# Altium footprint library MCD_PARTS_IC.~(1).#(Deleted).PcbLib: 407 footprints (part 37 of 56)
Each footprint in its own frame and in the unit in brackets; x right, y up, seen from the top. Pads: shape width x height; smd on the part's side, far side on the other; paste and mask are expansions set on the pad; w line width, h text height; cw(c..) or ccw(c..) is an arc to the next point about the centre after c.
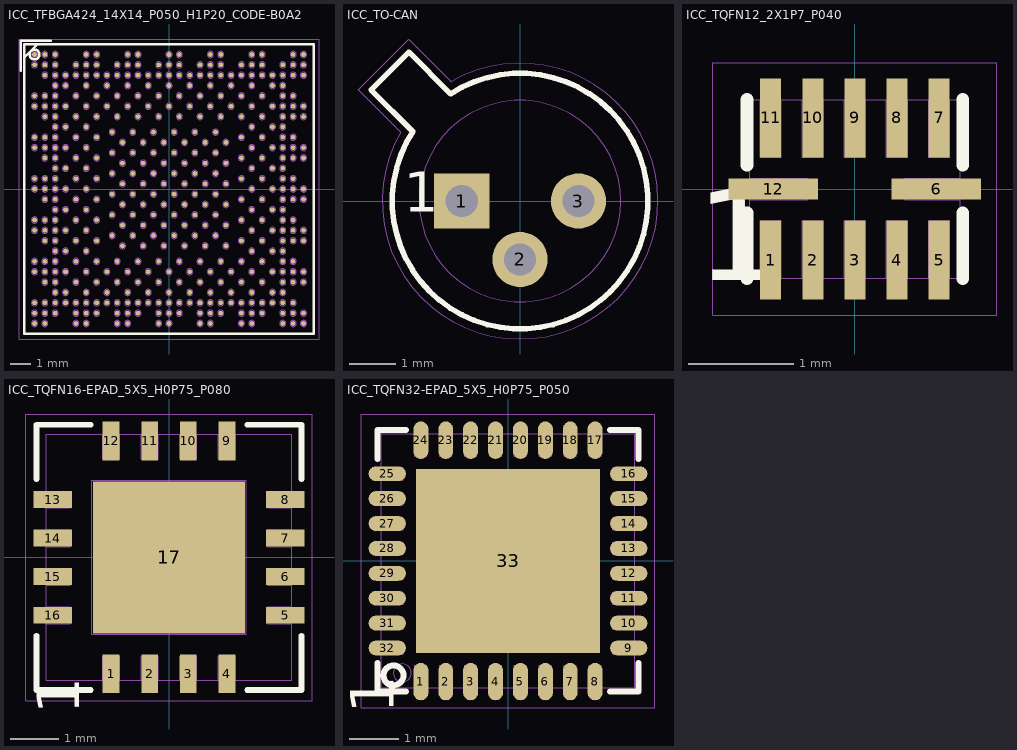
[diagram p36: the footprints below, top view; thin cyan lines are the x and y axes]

## ICC_TFBGA424_14X14_P050_H1P20_CODE-B0A2 [mm] "MCD_03375"
height 1.2
pads (424):
  round 0.23 smd paste+0.025 mask+0.05: 1A1(-2.75,2.75) 1A3(-1.75,2.75) 1A5(-0.75,2.75) 1A7(0.25,2.75) 1A9(1.25,2.75) 1A11(2.25,2.75) 1B2(-2.25,2.25) 1B4(-1.25,2.25) 1B6(-0.25,2.25) 1B8(0.75,2.25) 1B10(1.75,2.25) 1B12(2.75,2.25) 1C1(-2.75,1.75) 1C3(-1.75,1.75) 1C5(-0.75,1.75) 1C7(0.25,1.75) 1C9(1.25,1.75) 1C11(2.25,1.75) 1D2(-2.25,1.25) 1D4(-1.25,1.25) 1D6(-0.25,1.25) 1D8(0.75,1.25) 1D10(1.75,1.25) 1D12(2.75,1.25) 1E1(-2.75,0.75) 1E3(-1.75,0.75) 1E5(-0.75,0.75) 1E7(0.25,0.75) 1E9(1.25,0.75) 1E11(2.25,0.75) 1F2(-2.25,0.25) 1F4(-1.25,0.25) 1F6(-0.25,0.25) 1F8(0.75,0.25) 1F10(1.75,0.25) 1F12(2.75,0.25) 1G1(-2.75,-0.25) 1G3(-1.75,-0.25) 1G5(-0.75,-0.25) 1G7(0.25,-0.25) 1G9(1.25,-0.25) 1G11(2.25,-0.25) 1H2(-2.25,-0.75) 1H4(-1.25,-0.75) 1H6(-0.25,-0.75) 1H8(0.75,-0.75) 1H10(1.75,-0.75) 1H12(2.75,-0.75) 1J1(-2.75,-1.25) 1J3(-1.75,-1.25) 1J5(-0.75,-1.25) 1J7(0.25,-1.25) 1J9(1.25,-1.25) 1J11(2.25,-1.25) 1K2(-2.25,-1.75) 1K4(-1.25,-1.75) 1K6(-0.25,-1.75) 1K8(0.75,-1.75) 1K10(1.75,-1.75) 1K12(2.75,-1.75) 1L1(-2.75,-2.25) 1L3(-1.75,-2.25) 1L5(-0.75,-2.25) 1L7(0.25,-2.25) 1L9(1.25,-2.25) 1L11(2.25,-2.25) 1M2(-2.25,-2.75) 1M4(-1.25,-2.75) 1M6(-0.25,-2.75) 1M8(0.75,-2.75) 1M10(1.75,-2.75) 1M12(2.75,-2.75) A1(-6.5,6.5) A2(-6,6.5) A3(-5.5,6.5) A6(-4,6.5) A7(-3.5,6.5) A10(-2,6.5) A11(-1.5,6.5) A14(0,6.5) A15(0.5,6.5) A18(2,6.5) A19(2.5,6.5) A22(4,6.5) A23(4.5,6.5) A26(6,6.5) A27(6.5,6.5) AA1(-6.5,-3.5) AA2(-6,-3.5) AA3(-5.5,-3.5) AA5(-4.5,-3.5) AA7(-3.5,-3.5) AA9(-2.5,-3.5) AA11(-1.5,-3.5) AA13(-0.5,-3.5) AA15(0.5,-3.5) AA17(1.5,-3.5) AA19(2.5,-3.5) AA21(3.5,-3.5) AA23(4.5,-3.5) AA25(5.5,-3.5) AA26(6,-3.5) AB1(-6.5,-4) AB2(-6,-4) AB3(-5.5,-4) AB4(-5,-4) AB6(-4,-4) AB8(-3,-4) AB10(-2,-4) AB12(-1,-4) AB14(0,-4) AB16(1,-4) AB18(2,-4) AB20(3,-4) AB22(4,-4) AB24(5,-4) AB25(5.5,-4) AB26(6,-4) AB27(6.5,-4) AC2(-6,-4.5) AC3(-5.5,-4.5) AC5(-4.5,-4.5) AC7(-3.5,-4.5) AC9(-2.5,-4.5) AC11(-1.5,-4.5) AC13(-0.5,-4.5) AC15(0.5,-4.5) AC17(1.5,-4.5) AC19(2.5,-4.5) AC21(3.5,-4.5) AC23(4.5,-4.5) AC25(5.5,-4.5) AC26(6,-4.5) AC27(6.5,-4.5) AD3(-5.5,-5) AD4(-5,-5) AD6(-4,-5) AD8(-3,-5) AD10(-2,-5) AD12(-1,-5) AD14(0,-5) AD16(1,-5) AD18(2,-5) AD20(3,-5) AD22(4,-5) AD24(5,-5) AD25(5.5,-5) AE1(-6.5,-5.5) AE2(-6,-5.5) AE3(-5.5,-5.5) AE4(-5,-5.5) AE5(-4.5,-5.5) AE6(-4,-5.5) AE7(-3.5,-5.5) AE8(-3,-5.5) AE9(-2.5,-5.5) AE10(-2,-5.5) AE11(-1.5,-5.5) AE12(-1,-5.5) AE13(-0.5,-5.5) AE14(0,-5.5) AE15(0.5,-5.5) AE16(1,-5.5) AE17(1.5,-5.5) AE18(2,-5.5) AE19(2.5,-5.5) AE20(3,-5.5) AE21(3.5,-5.5) AE22(4,-5.5) AE23(4.5,-5.5) AE24(5,-5.5) AE25(5.5,-5.5) AE26(6,-5.5) AF1(-6.5,-6) AF2(-6,-6) AF3(-5.5,-6) AF5(-4.5,-6) AF6(-4,-6) AF7(-3.5,-6) AF9(-2.5,-6) AF10(-2,-6) AF11(-1.5,-6) AF13(-0.5,-6) AF14(0,-6) AF15(0.5,-6) AF17(1.5,-6) AF18(2,-6) AF19(2.5,-6) AF21(3.5,-6) AF22(4,-6) AF23(4.5,-6) AF25(5.5,-6) AF26(6,-6) AF27(6.5,-6) AG1(-6.5,-6.5) AG2(-6,-6.5) AG5(-4.5,-6.5) AG6(-4,-6.5) AG9(-2.5,-6.5) AG10(-2,-6.5) AG13(-0.5,-6.5) AG14(0,-6.5) AG17(1.5,-6.5) AG18(2,-6.5) AG21(3.5,-6.5) AG22(4,-6.5) AG25(5.5,-6.5) AG26(6,-6.5) AG27(6.5,-6.5) B1(-6.5,6) B2(-6,6) B3(-5.5,6) B5(-4.5,6) B6(-4,6) B7(-3.5,6) B9(-2.5,6) B10(-2,6) B11(-1.5,6) B13(-0.5,6) B14(0,6) B15(0.5,6) B17(1.5,6) B18(2,6) B19(2.5,6) B21(3.5,6) B22(4,6) B23(4.5,6) B25(5.5,6) B26(6,6) B27(6.5,6) C2(-6,5.5) C3(-5.5,5.5) C4(-5,5.5) C5(-4.5,5.5) C6(-4,5.5) C7(-3.5,5.5) C8(-3,5.5) C9(-2.5,5.5) C10(-2,5.5) C11(-1.5,5.5) C12(-1,5.5) C13(-0.5,5.5) C14(0,5.5) C15(0.5,5.5) C16(1,5.5) C17(1.5,5.5) C18(2,5.5) C19(2.5,5.5) C20(3,5.5) C21(3.5,5.5) C22(4,5.5) C23(4.5,5.5) C24(5,5.5) C25(5.5,5.5) C26(6,5.5) C27(6.5,5.5) D3(-5.5,5) D4(-5,5) D6(-4,5) D8(-3,5) D10(-2,5) D12(-1,5) D14(0,5) D16(1,5) D18(2,5) D20(3,5) D22(4,5) D24(5,5) D25(5.5,5) E1(-6.5,4.5) E2(-6,4.5) E3(-5.5,4.5) E5(-4.5,4.5) E7(-3.5,4.5) E9(-2.5,4.5) E11(-1.5,4.5) E13(-0.5,4.5) E15(0.5,4.5) E17(1.5,4.5) E19(2.5,4.5) E21(3.5,4.5) E23(4.5,4.5) E25(5.5,4.5) E26(6,4.5) F1(-6.5,4) F2(-6,4) F3(-5.5,4) F4(-5,4) F6(-4,4) F8(-3,4) F10(-2,4) F12(-1,4) F14(0,4) F16(1,4) F18(2,4) F20(3,4) F22(4,4) F24(5,4) F25(5.5,4) F26(6,4) F27(6.5,4) G2(-6,3.5) G3(-5.5,3.5) G5(-4.5,3.5) G7(-3.5,3.5) G9(-2.5,3.5) G11(-1.5,3.5) G13(-0.5,3.5) G15(0.5,3.5) G17(1.5,3.5) G19(2.5,3.5) G21(3.5,3.5) G23(4.5,3.5) G25(5.5,3.5) G26(6,3.5) G27(6.5,3.5) H3(-5.5,3) H4(-5,3) H6(-4,3) H22(4,3) H24(5,3) H25(5.5,3) J1(-6.5,2.5) J2(-6,2.5) J3(-5.5,2.5) J5(-4.5,2.5) J7(-3.5,2.5) J21(3.5,2.5) J23(4.5,2.5) J25(5.5,2.5) J26(6,2.5) K1(-6.5,2) K2(-6,2) K3(-5.5,2) K4(-5,2) K6(-4,2) K22(4,2) K24(5,2) K25(5.5,2) K26(6,2) K27(6.5,2) L2(-6,1.5) L3(-5.5,1.5) L5(-4.5,1.5) L7(-3.5,1.5) L21(3.5,1.5) L23(4.5,1.5) L25(5.5,1.5) L26(6,1.5) L27(6.5,1.5) M3(-5.5,1) M4(-5,1) M6(-4,1) M22(4,1) M24(5,1) M25(5.5,1) N1(-6.5,0.5) N2(-6,0.5) N3(-5.5,0.5) N5(-4.5,0.5) N7(-3.5,0.5) N21(3.5,0.5) N23(4.5,0.5) N25(5.5,0.5) N26(6,0.5) P1(-6.5,0) P2(-6,0) P3(-5.5,0) P4(-5,0) P6(-4,0) P22(4,0) P24(5,0) P25(5.5,0) P26(6,0) P27(6.5,0) R2(-6,-0.5) R3(-5.5,-0.5) R5(-4.5,-0.5) R7(-3.5,-0.5) R21(3.5,-0.5) R23(4.5,-0.5) R25(5.5,-0.5) R26(6,-0.5) R27(6.5,-0.5) T3(-5.5,-1) T4(-5,-1) T6(-4,-1) T22(4,-1) T24(5,-1) T25(5.5,-1) U1(-6.5,-1.5) U2(-6,-1.5) U3(-5.5,-1.5) U5(-4.5,-1.5) U7(-3.5,-1.5) U21(3.5,-1.5) U23(4.5,-1.5) U25(5.5,-1.5) U26(6,-1.5) V1(-6.5,-2) V2(-6,-2) V3(-5.5,-2) V4(-5,-2) V6(-4,-2) V22(4,-2) V24(5,-2) V25(5.5,-2) V26(6,-2) V27(6.5,-2) W2(-6,-2.5) W3(-5.5,-2.5) W5(-4.5,-2.5) W7(-3.5,-2.5) W21(3.5,-2.5) W23(4.5,-2.5) W25(5.5,-2.5) W26(6,-2.5) W27(6.5,-2.5) Y3(-5.5,-3) Y4(-5,-3) Y6(-4,-3) Y22(4,-3) Y24(5,-3) Y25(5.5,-3)
Top Overlay:
  circle w0.12: c-6.5,6.5 r0.24
  lines w0.12: -7.175,5.725 -7.175,7.175 -5.725,7.175 ; -7,6.345 -6.345,7 ; -7,-7 -7,7 7,7 7,-7 -7,-7
M14-Top Assembly:
  drawing of 429 lines, arcs and shapes, not listed
  text "'.Designator'" at 0,0 h0.75
  text "A1" at -6.75,6.3 h0.4
M16-Top Courtyard:
  lines w0.01: -7.25,-7.25 7.25,-7.25 7.25,7.25 -7.25,7.25 -7.25,-7.25
3D body: height 0.27, standoff -0.03, extent -2.4,-0.898 -2.109,-0.603
3D body: height 0.27, standoff -0.03, extent 0.1,-0.398 0.391,-0.103
3D body: height 0.27, standoff -0.03, extent -0.4,0.102 -0.109,0.397
3D body: height 0.27, standoff -0.03, extent 1.1,-0.398 1.391,-0.103
3D body: height 0.27, standoff -0.03, extent -0.9,-0.398 -0.609,-0.103
3D body: height 0.27, standoff -0.03, extent -1.9,-0.398 -1.609,-0.103
3D body: height 0.27, standoff -0.03, extent -2.9,-0.398 -2.609,-0.103
3D body: height 0.27, standoff -0.03, extent -1.4,0.102 -1.109,0.397
3D body: height 0.27, standoff -0.03, extent -2.4,0.102 -2.109,0.397
3D body: height 0.27, standoff -0.03, extent 0.609,0.102 0.9,0.398
3D body: height 0.27, standoff -0.03, extent 1.609,0.102 1.9,0.398
3D body: height 0.27, standoff -0.03, extent 2.609,0.102 2.9,0.398
3D body: height 0.27, standoff -0.03, extent 2.109,-0.398 2.4,-0.102
3D body: height 0.27, standoff -0.03, extent 0.103,-1.4 0.398,-1.109
3D body: height 0.27, standoff -0.03, extent 0.103,-2.4 0.398,-2.109
3D body: height 0.27, standoff -0.03, extent -0.397,-0.9 -0.102,-0.609
3D body: height 0.27, standoff -0.03, extent -0.397,-1.9 -0.102,-1.609
3D body: height 0.27, standoff -0.03, extent -0.397,-2.9 -0.102,-2.609
3D body: height 0.27, standoff -0.03, extent 0.102,0.609 0.398,0.9
3D body: height 0.27, standoff -0.03, extent 0.102,1.609 0.398,1.9
3D body: height 0.27, standoff -0.03, extent 0.102,2.609 0.398,2.9
3D body: height 0.27, standoff -0.03, extent -0.398,1.109 -0.102,1.4
3D body: height 0.27, standoff -0.03, extent -0.398,2.109 -0.102,2.4
3D body: height 0.27, standoff -0.03, extent 1.109,2.602 1.4,2.898
3D body: height 0.27, standoff -0.03, extent 2.109,2.602 2.4,2.898
3D body: height 0.27, standoff -0.03, extent 0.609,2.102 0.9,2.398
3D body: height 0.27, standoff -0.03, extent 1.609,2.102 1.9,2.398
3D body: height 0.27, standoff -0.03, extent 2.609,2.102 2.9,2.398
3D body: height 0.27, standoff -0.03, extent 1.109,1.602 1.4,1.898
3D body: height 0.27, standoff -0.03, extent 2.109,1.602 2.4,1.898
3D body: height 0.27, standoff -0.03, extent 0.609,1.102 0.9,1.398
3D body: height 0.27, standoff -0.03, extent 1.609,1.102 1.9,1.398
3D body: height 0.27, standoff -0.03, extent 2.609,1.102 2.9,1.398
3D body: height 0.27, standoff -0.03, extent 1.109,0.602 1.4,0.898
3D body: height 0.27, standoff -0.03, extent 2.109,0.602 2.4,0.898
3D body: height 0.27, standoff -0.03, extent -0.9,0.602 -0.609,0.897
3D body: height 0.27, standoff -0.03, extent -1.9,0.602 -1.609,0.897
3D body: height 0.27, standoff -0.03, extent -2.9,0.602 -2.609,0.897
3D body: height 0.27, standoff -0.03, extent -1.4,1.102 -1.109,1.397
3D body: height 0.27, standoff -0.03, extent -2.4,1.102 -2.109,1.397
3D body: height 0.27, standoff -0.03, extent -0.9,1.602 -0.609,1.897
3D body: height 0.27, standoff -0.03, extent -1.9,1.602 -1.609,1.897
3D body: height 0.27, standoff -0.03, extent -2.9,1.602 -2.609,1.897
3D body: height 0.27, standoff -0.03, extent -1.4,2.102 -1.109,2.397
3D body: height 0.27, standoff -0.03, extent -0.9,2.602 -0.609,2.897
3D body: height 0.27, standoff -0.03, extent -1.9,2.602 -1.609,2.897
3D body: height 0.27, standoff -0.03, extent -2.4,2.102 -2.109,2.397
3D body: height 0.27, standoff -0.03, extent -2.9,2.602 -2.609,2.897
3D body: height 0.27, standoff -0.03, extent 0.609,-0.898 0.9,-0.602
3D body: height 0.27, standoff -0.03, extent 1.609,-0.898 1.9,-0.602
3D body: height 0.27, standoff -0.03, extent 2.609,-0.898 2.9,-0.602
3D body: height 0.27, standoff -0.03, extent 1.109,-1.398 1.4,-1.102
3D body: height 0.27, standoff -0.03, extent 2.109,-1.398 2.4,-1.102
3D body: height 0.27, standoff -0.03, extent 0.609,-1.898 0.9,-1.602
3D body: height 0.27, standoff -0.03, extent 1.609,-1.898 1.9,-1.602
3D body: height 0.27, standoff -0.03, extent 2.609,-1.898 2.9,-1.602
3D body: height 0.27, standoff -0.03, extent 1.109,-2.398 1.4,-2.102
3D body: height 0.27, standoff -0.03, extent 2.109,-2.398 2.4,-2.102
3D body: height 0.27, standoff -0.03, extent 0.609,-2.898 0.9,-2.602
3D body: height 0.27, standoff -0.03, extent 1.609,-2.898 1.9,-2.602
3D body: height 0.27, standoff -0.03, extent 2.609,-2.898 2.9,-2.602
3D body: height 0.27, standoff -0.03, extent -1.4,-2.898 -1.109,-2.603
3D body: height 0.27, standoff -0.03, extent -2.4,-2.898 -2.109,-2.603
3D body: height 0.27, standoff -0.03, extent -0.9,-2.398 -0.609,-2.103
3D body: height 0.27, standoff -0.03, extent -1.9,-2.398 -1.609,-2.103
3D body: height 0.27, standoff -0.03, extent -2.9,-2.398 -2.609,-2.103
3D body: height 0.27, standoff -0.03, extent -1.4,-1.898 -1.109,-1.603
3D body: height 0.27, standoff -0.03, extent -2.4,-1.898 -2.109,-1.603
3D body: height 0.27, standoff -0.03, extent -0.9,-1.398 -0.609,-1.103
3D body: height 0.27, standoff -0.03, extent -1.9,-1.398 -1.609,-1.103
3D body: height 0.27, standoff -0.03, extent -2.9,-1.398 -2.609,-1.103
3D body: height 0.27, standoff -0.03, extent -1.4,-0.898 -1.109,-0.603
3D body: height 0.32, standoff -0.08, extent 3.301,-3.697 3.7,-3.303
3D body: height 0.32, standoff -0.08, extent 2.301,-3.697 2.7,-3.303
3D body: height 0.32, standoff -0.08, extent 1.301,-3.697 1.7,-3.303
3D body: height 0.32, standoff -0.08, extent 0.301,-3.697 0.7,-3.303
3D body: height 0.32, standoff -0.08, extent -0.699,-3.697 -0.3,-3.303
3D body: height 0.32, standoff -0.08, extent -1.699,-3.697 -1.3,-3.303
3D body: height 0.32, standoff -0.08, extent -2.699,-3.697 -2.3,-3.303
3D body: height 0.32, standoff -0.08, extent -3.699,-3.697 -3.3,-3.303
3D body: height 0.32, standoff -0.08, extent -3.699,3.303 -3.3,3.697
3D body: height 0.32, standoff -0.08, extent -2.699,3.303 -2.3,3.697
3D body: height 0.32, standoff -0.08, extent -1.699,3.303 -1.3,3.697
3D body: height 0.32, standoff -0.08, extent -0.699,3.303 -0.3,3.697
3D body: height 0.32, standoff -0.08, extent 0.301,3.303 0.7,3.697
3D body: height 0.32, standoff -0.08, extent 1.301,3.303 1.7,3.697
3D body: height 0.32, standoff -0.08, extent 2.301,3.303 2.7,3.697
3D body: height 0.32, standoff -0.08, extent 3.301,3.303 3.7,3.697
3D body: height 1.2, standoff 0.23, extent -7,-7 7,7
3D body: height 1.21, standoff 1.2, extent -6.798,6.201 -6.2,6.8
3D body: height 0.32, standoff -0.08, extent -6.699,-6.197 -6.3,-5.803
3D body: height 0.32, standoff -0.08, extent -6.699,-5.697 -6.3,-5.303
3D body: height 0.32, standoff -0.08, extent -6.699,-4.197 -6.3,-3.803
3D body: height 0.32, standoff -0.08, extent -6.699,-3.697 -6.3,-3.303
3D body: height 0.32, standoff -0.08, extent -6.699,-2.197 -6.3,-1.803
3D body: height 0.32, standoff -0.08, extent -6.699,-1.697 -6.3,-1.303
3D body: height 0.32, standoff -0.08, extent -6.699,-0.197 -6.3,0.197
3D body: height 0.32, standoff -0.08, extent -6.699,0.303 -6.3,0.697
3D body: height 0.32, standoff -0.08, extent -6.699,1.803 -6.3,2.197
3D body: height 0.32, standoff -0.08, extent -6.699,2.303 -6.3,2.697
3D body: height 0.32, standoff -0.08, extent -6.699,3.803 -6.3,4.197
3D body: height 0.32, standoff -0.08, extent -6.699,4.303 -6.3,4.697
3D body: height 0.32, standoff -0.08, extent -6.699,5.803 -6.3,6.197
3D body: height 0.32, standoff -0.08, extent -6.699,6.303 -6.3,6.697
3D body: height 0.32, standoff -0.08, extent -6.199,-6.197 -5.8,-5.803
3D body: height 0.32, standoff -0.08, extent -6.199,-5.697 -5.8,-5.303
3D body: height 0.32, standoff -0.08, extent -6.199,-4.697 -5.8,-4.303
3D body: height 0.32, standoff -0.08, extent -6.199,-4.197 -5.8,-3.803
3D body: height 0.32, standoff -0.08, extent -6.199,-3.697 -5.8,-3.303
3D body: height 0.32, standoff -0.08, extent -6.199,-2.697 -5.8,-2.303
3D body: height 0.32, standoff -0.08, extent -6.199,-2.197 -5.8,-1.803
3D body: height 0.32, standoff -0.08, extent -6.199,-1.697 -5.8,-1.303
3D body: height 0.32, standoff -0.08, extent -6.199,-0.697 -5.8,-0.303
3D body: height 0.32, standoff -0.08, extent -6.199,-0.197 -5.8,0.197
3D body: height 0.32, standoff -0.08, extent -6.199,0.303 -5.8,0.697
3D body: height 0.32, standoff -0.08, extent -6.199,1.303 -5.8,1.697
3D body: height 0.32, standoff -0.08, extent -6.199,1.803 -5.8,2.197
3D body: height 0.32, standoff -0.08, extent -6.199,2.303 -5.8,2.697
3D body: height 0.32, standoff -0.08, extent -6.199,3.303 -5.8,3.697
3D body: height 0.32, standoff -0.08, extent -6.199,3.803 -5.8,4.197
3D body: height 0.32, standoff -0.08, extent -6.199,4.303 -5.8,4.697
3D body: height 0.32, standoff -0.08, extent -6.199,5.303 -5.8,5.697
3D body: height 0.32, standoff -0.08, extent -6.199,5.803 -5.8,6.197
3D body: height 0.32, standoff -0.08, extent -6.199,6.303 -5.8,6.697
3D body: height 0.32, standoff -0.08, extent -5.699,-6.197 -5.3,-5.803
3D body: height 0.32, standoff -0.08, extent -5.699,-5.697 -5.3,-5.303
3D body: height 0.32, standoff -0.08, extent -5.699,-5.197 -5.3,-4.803
3D body: height 0.32, standoff -0.08, extent -5.699,-4.697 -5.3,-4.303
3D body: height 0.32, standoff -0.08, extent -5.699,-4.197 -5.3,-3.803
3D body: height 0.32, standoff -0.08, extent -5.699,-3.697 -5.3,-3.303
3D body: height 0.32, standoff -0.08, extent -5.699,-3.197 -5.3,-2.803
3D body: height 0.32, standoff -0.08, extent -5.699,-2.697 -5.3,-2.303
3D body: height 0.32, standoff -0.08, extent -5.699,-2.197 -5.3,-1.803
3D body: height 0.32, standoff -0.08, extent -5.699,-1.697 -5.3,-1.303
3D body: height 0.32, standoff -0.08, extent -5.699,-1.197 -5.3,-0.803
3D body: height 0.32, standoff -0.08, extent -5.699,-0.697 -5.3,-0.303
3D body: height 0.32, standoff -0.08, extent -5.699,-0.197 -5.3,0.197
3D body: height 0.32, standoff -0.08, extent -5.699,0.303 -5.3,0.697
3D body: height 0.32, standoff -0.08, extent -5.699,0.803 -5.3,1.197
3D body: height 0.32, standoff -0.08, extent -5.699,1.303 -5.3,1.697
3D body: height 0.32, standoff -0.08, extent -5.699,1.803 -5.3,2.197
3D body: height 0.32, standoff -0.08, extent -5.699,2.303 -5.3,2.697
3D body: height 0.32, standoff -0.08, extent -5.699,2.803 -5.3,3.197
3D body: height 0.32, standoff -0.08, extent -5.699,3.303 -5.3,3.697
3D body: height 0.32, standoff -0.08, extent -5.699,3.803 -5.3,4.197
3D body: height 0.32, standoff -0.08, extent -5.699,4.303 -5.3,4.697
3D body: height 0.32, standoff -0.08, extent -5.699,4.803 -5.3,5.197
3D body: height 0.32, standoff -0.08, extent -5.699,5.303 -5.3,5.697
3D body: height 0.32, standoff -0.08, extent -5.699,5.803 -5.3,6.197
3D body: height 0.32, standoff -0.08, extent -5.699,6.303 -5.3,6.697
3D body: height 0.32, standoff -0.08, extent -5.199,-5.697 -4.8,-5.303
3D body: height 0.32, standoff -0.08, extent -5.199,-5.197 -4.8,-4.803
3D body: height 0.32, standoff -0.08, extent -5.199,-4.197 -4.8,-3.803
3D body: height 0.32, standoff -0.08, extent -5.199,-3.197 -4.8,-2.803
3D body: height 0.32, standoff -0.08, extent -5.199,-2.197 -4.8,-1.803
3D body: height 0.32, standoff -0.08, extent -5.199,-1.197 -4.8,-0.803
3D body: height 0.32, standoff -0.08, extent -5.199,-0.197 -4.8,0.197
3D body: height 0.32, standoff -0.08, extent -5.199,0.803 -4.8,1.197
3D body: height 0.32, standoff -0.08, extent -5.199,1.803 -4.8,2.197
3D body: height 0.32, standoff -0.08, extent -5.199,2.803 -4.8,3.197
3D body: height 0.32, standoff -0.08, extent -5.199,3.803 -4.8,4.197
3D body: height 0.32, standoff -0.08, extent -5.199,4.803 -4.8,5.197
3D body: height 0.32, standoff -0.08, extent -5.199,5.303 -4.8,5.697
3D body: height 0.32, standoff -0.08, extent -4.699,-6.197 -4.3,-5.803
3D body: height 0.32, standoff -0.08, extent -4.699,-5.697 -4.3,-5.303
3D body: height 0.32, standoff -0.08, extent -4.699,-4.697 -4.3,-4.303
3D body: height 0.32, standoff -0.08, extent -4.699,-3.697 -4.3,-3.303
3D body: height 0.32, standoff -0.08, extent -4.699,-2.697 -4.3,-2.303
3D body: height 0.32, standoff -0.08, extent -4.699,-1.697 -4.3,-1.303
3D body: height 0.32, standoff -0.08, extent -4.699,-0.697 -4.3,-0.303
3D body: height 0.32, standoff -0.08, extent -4.699,0.303 -4.3,0.697
3D body: height 0.32, standoff -0.08, extent -4.699,1.303 -4.3,1.697
3D body: height 0.32, standoff -0.08, extent -4.699,2.303 -4.3,2.697
3D body: height 0.32, standoff -0.08, extent -4.699,3.303 -4.3,3.697
3D body: height 0.32, standoff -0.08, extent -4.699,4.303 -4.3,4.697
3D body: height 0.32, standoff -0.08, extent -4.699,5.303 -4.3,5.697
3D body: height 0.32, standoff -0.08, extent -4.699,5.803 -4.3,6.197
3D body: height 0.32, standoff -0.08, extent -4.199,-6.197 -3.8,-5.803
3D body: height 0.32, standoff -0.08, extent -4.199,-5.697 -3.8,-5.303
3D body: height 0.32, standoff -0.08, extent -4.199,-5.197 -3.8,-4.803
3D body: height 0.32, standoff -0.08, extent -4.199,4.803 -3.8,5.197
3D body: height 0.32, standoff -0.08, extent -4.199,5.303 -3.8,5.697
3D body: height 0.32, standoff -0.08, extent -4.199,5.803 -3.8,6.197
3D body: height 0.32, standoff -0.08, extent -4.199,6.303 -3.8,6.697
3D body: height 0.32, standoff -0.08, extent -3.699,-6.197 -3.3,-5.803
3D body: height 0.32, standoff -0.08, extent -3.699,-5.697 -3.3,-5.303
3D body: height 0.32, standoff -0.08, extent -3.699,-4.697 -3.3,-4.303
3D body: height 0.32, standoff -0.08, extent -3.699,5.303 -3.3,5.697
3D body: height 0.32, standoff -0.08, extent -3.699,5.803 -3.3,6.197
3D body: height 0.32, standoff -0.08, extent -3.699,6.303 -3.3,6.697
3D body: height 0.32, standoff -0.08, extent -3.199,-5.697 -2.8,-5.303
3D body: height 0.32, standoff -0.08, extent -3.199,-5.197 -2.8,-4.803
3D body: height 0.32, standoff -0.08, extent -3.199,4.803 -2.8,5.197
3D body: height 0.32, standoff -0.08, extent -3.199,5.303 -2.8,5.697
3D body: height 0.32, standoff -0.08, extent -2.699,-6.197 -2.3,-5.803
3D body: height 0.32, standoff -0.08, extent -2.699,-5.697 -2.3,-5.303
3D body: height 0.32, standoff -0.08, extent -2.699,-4.697 -2.3,-4.303
3D body: height 0.32, standoff -0.08, extent -2.699,5.303 -2.3,5.697
3D body: height 0.32, standoff -0.08, extent -2.699,5.803 -2.3,6.197
3D body: height 0.32, standoff -0.08, extent -2.199,-6.197 -1.8,-5.803
3D body: height 0.32, standoff -0.08, extent -2.199,-5.697 -1.8,-5.303
3D body: height 0.32, standoff -0.08, extent -2.199,-5.197 -1.8,-4.803
3D body: height 0.32, standoff -0.08, extent -2.199,4.803 -1.8,5.197
3D body: height 0.32, standoff -0.08, extent -2.199,5.303 -1.8,5.697
3D body: height 0.32, standoff -0.08, extent -2.199,5.803 -1.8,6.197
3D body: height 0.32, standoff -0.08, extent -2.199,6.303 -1.8,6.697
3D body: height 0.32, standoff -0.08, extent -1.699,-6.197 -1.3,-5.803
3D body: height 0.32, standoff -0.08, extent -1.699,-5.697 -1.3,-5.303
3D body: height 0.32, standoff -0.08, extent -1.699,-4.697 -1.3,-4.303
3D body: height 0.32, standoff -0.08, extent -1.699,5.303 -1.3,5.697
3D body: height 0.32, standoff -0.08, extent -1.699,5.803 -1.3,6.197
3D body: height 0.32, standoff -0.08, extent -1.699,6.303 -1.3,6.697
3D body: height 0.32, standoff -0.08, extent -1.199,-5.697 -0.8,-5.303
3D body: height 0.32, standoff -0.08, extent -1.199,-5.197 -0.8,-4.803
3D body: height 0.32, standoff -0.08, extent -1.199,4.803 -0.8,5.197
3D body: height 0.32, standoff -0.08, extent -1.199,5.303 -0.8,5.697
3D body: height 0.32, standoff -0.08, extent -0.699,-6.197 -0.3,-5.803
3D body: height 0.32, standoff -0.08, extent -0.699,-5.697 -0.3,-5.303
3D body: height 0.32, standoff -0.08, extent -0.699,-4.697 -0.3,-4.303
3D body: height 0.32, standoff -0.08, extent -0.699,5.303 -0.3,5.697
3D body: height 0.32, standoff -0.08, extent -0.699,5.803 -0.3,6.197
3D body: height 0.32, standoff -0.08, extent -0.199,-6.197 0.2,-5.803
3D body: height 0.32, standoff -0.08, extent -0.199,-5.697 0.2,-5.303
3D body: height 0.32, standoff -0.08, extent -0.199,-5.197 0.2,-4.803
3D body: height 0.32, standoff -0.08, extent -0.199,4.803 0.2,5.197
3D body: height 0.32, standoff -0.08, extent -0.199,5.303 0.2,5.697
3D body: height 0.32, standoff -0.08, extent -0.199,5.803 0.2,6.197
3D body: height 0.32, standoff -0.08, extent -0.199,6.303 0.2,6.697
3D body: height 0.32, standoff -0.08, extent 0.301,-6.197 0.7,-5.803
3D body: height 0.32, standoff -0.08, extent 0.301,-5.697 0.7,-5.303
3D body: height 0.32, standoff -0.08, extent 0.301,-4.697 0.7,-4.303
3D body: height 0.32, standoff -0.08, extent 0.301,5.303 0.7,5.697
3D body: height 0.32, standoff -0.08, extent 0.301,5.803 0.7,6.197
3D body: height 0.32, standoff -0.08, extent 0.301,6.303 0.7,6.697
3D body: height 0.32, standoff -0.08, extent 0.801,-5.697 1.2,-5.303
3D body: height 0.32, standoff -0.08, extent 0.801,-5.197 1.2,-4.803
3D body: height 0.32, standoff -0.08, extent 0.801,4.803 1.2,5.197
3D body: height 0.32, standoff -0.08, extent 0.801,5.303 1.2,5.697
3D body: height 0.32, standoff -0.08, extent 1.301,-6.197 1.7,-5.803
3D body: height 0.32, standoff -0.08, extent 1.301,-5.697 1.7,-5.303
3D body: height 0.32, standoff -0.08, extent 1.301,-4.697 1.7,-4.303
3D body: height 0.32, standoff -0.08, extent 1.301,5.303 1.7,5.697
3D body: height 0.32, standoff -0.08, extent 1.301,5.803 1.7,6.197
3D body: height 0.32, standoff -0.08, extent 1.801,-6.197 2.2,-5.803
3D body: height 0.32, standoff -0.08, extent 1.801,-5.697 2.2,-5.303
3D body: height 0.32, standoff -0.08, extent 1.801,-5.197 2.2,-4.803
3D body: height 0.32, standoff -0.08, extent 1.801,4.803 2.2,5.197
3D body: height 0.32, standoff -0.08, extent 1.801,5.303 2.2,5.697
3D body: height 0.32, standoff -0.08, extent 1.801,5.803 2.2,6.197
3D body: height 0.32, standoff -0.08, extent 1.801,6.303 2.2,6.697
3D body: height 0.32, standoff -0.08, extent 2.301,-6.197 2.7,-5.803
3D body: height 0.32, standoff -0.08, extent 2.301,-5.697 2.7,-5.303
3D body: height 0.32, standoff -0.08, extent 2.301,-4.697 2.7,-4.303
3D body: height 0.32, standoff -0.08, extent 2.301,5.303 2.7,5.697
3D body: height 0.32, standoff -0.08, extent 2.301,5.803 2.7,6.197
3D body: height 0.32, standoff -0.08, extent 2.301,6.303 2.7,6.697
3D body: height 0.32, standoff -0.08, extent 2.801,-5.697 3.2,-5.303
3D body: height 0.32, standoff -0.08, extent 2.801,-5.197 3.2,-4.803
3D body: height 0.32, standoff -0.08, extent 2.801,4.803 3.2,5.197
3D body: height 0.32, standoff -0.08, extent 2.801,5.303 3.2,5.697
3D body: height 0.32, standoff -0.08, extent 3.301,-6.197 3.7,-5.803
3D body: height 0.32, standoff -0.08, extent 3.301,-5.697 3.7,-5.303
3D body: height 0.32, standoff -0.08, extent 3.301,-4.697 3.7,-4.303
3D body: height 0.32, standoff -0.08, extent 3.301,5.303 3.7,5.697
3D body: height 0.32, standoff -0.08, extent 3.301,5.803 3.7,6.197
3D body: height 0.32, standoff -0.08, extent 3.801,-6.197 4.2,-5.803
3D body: height 0.32, standoff -0.08, extent 3.801,-5.697 4.2,-5.303
3D body: height 0.32, standoff -0.08, extent 3.801,-5.197 4.2,-4.803
3D body: height 0.32, standoff -0.08, extent 3.801,-2.197 4.2,-1.803
3D body: height 0.32, standoff -0.08, extent 3.801,-1.197 4.2,-0.803
3D body: height 0.32, standoff -0.08, extent 3.801,-0.197 4.2,0.197
3D body: height 0.32, standoff -0.08, extent 3.801,0.803 4.2,1.197
3D body: height 0.32, standoff -0.08, extent 3.801,4.803 4.2,5.197
3D body: height 0.32, standoff -0.08, extent 3.801,5.303 4.2,5.697
3D body: height 0.32, standoff -0.08, extent 3.801,5.803 4.2,6.197
3D body: height 0.32, standoff -0.08, extent 3.801,6.303 4.2,6.697
3D body: height 0.32, standoff -0.08, extent 4.301,-6.197 4.7,-5.803
3D body: height 0.32, standoff -0.08, extent 4.301,-5.697 4.7,-5.303
3D body: height 0.32, standoff -0.08, extent 4.301,-4.697 4.7,-4.303
3D body: height 0.32, standoff -0.08, extent 4.301,-3.697 4.7,-3.303
3D body: height 0.32, standoff -0.08, extent 4.301,-2.697 4.7,-2.303
3D body: height 0.32, standoff -0.08, extent 4.301,-1.697 4.7,-1.303
3D body: height 0.32, standoff -0.08, extent 4.301,-0.697 4.7,-0.303
3D body: height 0.32, standoff -0.08, extent 4.301,0.303 4.7,0.697
3D body: height 0.32, standoff -0.08, extent 4.301,1.303 4.7,1.697
3D body: height 0.32, standoff -0.08, extent 4.301,2.303 4.7,2.697
3D body: height 0.32, standoff -0.08, extent 4.301,3.303 4.7,3.697
3D body: height 0.32, standoff -0.08, extent 4.301,4.303 4.7,4.697
3D body: height 0.32, standoff -0.08, extent 4.301,5.303 4.7,5.697
3D body: height 0.32, standoff -0.08, extent 4.301,5.803 4.7,6.197
3D body: height 0.32, standoff -0.08, extent 4.301,6.303 4.7,6.697
3D body: height 0.32, standoff -0.08, extent 4.801,-5.697 5.2,-5.303
3D body: height 0.32, standoff -0.08, extent 4.801,-5.197 5.2,-4.803
3D body: height 0.32, standoff -0.08, extent 4.801,-4.197 5.2,-3.803
3D body: height 0.32, standoff -0.08, extent 4.801,-3.197 5.2,-2.803
3D body: height 0.32, standoff -0.08, extent 4.801,-2.197 5.2,-1.803
3D body: height 0.32, standoff -0.08, extent 4.801,-1.197 5.2,-0.803
3D body: height 0.32, standoff -0.08, extent 4.801,-0.197 5.2,0.197
3D body: height 0.32, standoff -0.08, extent 4.801,0.803 5.2,1.197
3D body: height 0.32, standoff -0.08, extent 4.801,1.803 5.2,2.197
3D body: height 0.32, standoff -0.08, extent 4.801,2.803 5.2,3.197
3D body: height 0.32, standoff -0.08, extent 4.801,3.803 5.2,4.197
3D body: height 0.32, standoff -0.08, extent 4.801,4.803 5.2,5.197
3D body: height 0.32, standoff -0.08, extent 4.801,5.303 5.2,5.697
3D body: height 0.32, standoff -0.08, extent 5.301,-6.197 5.7,-5.803
3D body: height 0.32, standoff -0.08, extent 5.301,-5.697 5.7,-5.303
3D body: height 0.32, standoff -0.08, extent 5.301,-5.197 5.7,-4.803
3D body: height 0.32, standoff -0.08, extent 5.301,-4.697 5.7,-4.303
3D body: height 0.32, standoff -0.08, extent 5.301,-4.197 5.7,-3.803
3D body: height 0.32, standoff -0.08, extent 5.301,-3.697 5.7,-3.303
3D body: height 0.32, standoff -0.08, extent 5.301,-3.197 5.7,-2.803
3D body: height 0.32, standoff -0.08, extent 5.301,-2.697 5.7,-2.303
3D body: height 0.32, standoff -0.08, extent 5.301,-2.197 5.7,-1.803
3D body: height 0.32, standoff -0.08, extent 5.301,-1.697 5.7,-1.303
3D body: height 0.32, standoff -0.08, extent 5.301,-1.197 5.7,-0.803
3D body: height 0.32, standoff -0.08, extent 5.301,-0.697 5.7,-0.303
3D body: height 0.32, standoff -0.08, extent 5.301,-0.197 5.7,0.197
3D body: height 0.32, standoff -0.08, extent 5.301,0.303 5.7,0.697
3D body: height 0.32, standoff -0.08, extent 5.301,0.803 5.7,1.197
3D body: height 0.32, standoff -0.08, extent 5.301,1.303 5.7,1.697
3D body: height 0.32, standoff -0.08, extent 5.301,1.803 5.7,2.197
3D body: height 0.32, standoff -0.08, extent 5.301,2.303 5.7,2.697
3D body: height 0.32, standoff -0.08, extent 5.301,2.803 5.7,3.197
3D body: height 0.32, standoff -0.08, extent 5.301,3.303 5.7,3.697
3D body: height 0.32, standoff -0.08, extent 5.301,3.803 5.7,4.197
3D body: height 0.32, standoff -0.08, extent 5.301,4.303 5.7,4.697
3D body: height 0.32, standoff -0.08, extent 5.301,4.803 5.7,5.197
3D body: height 0.32, standoff -0.08, extent 5.301,5.303 5.7,5.697
3D body: height 0.32, standoff -0.08, extent 5.301,5.803 5.7,6.197
3D body: height 0.32, standoff -0.08, extent 5.801,-6.197 6.2,-5.803
3D body: height 0.32, standoff -0.08, extent 5.801,-5.697 6.2,-5.303
3D body: height 0.32, standoff -0.08, extent 5.801,-4.697 6.2,-4.303
3D body: height 0.32, standoff -0.08, extent 5.801,-4.197 6.2,-3.803
3D body: height 0.32, standoff -0.08, extent 5.801,-3.697 6.2,-3.303
3D body: height 0.32, standoff -0.08, extent 5.801,-2.697 6.2,-2.303
3D body: height 0.32, standoff -0.08, extent 5.801,-2.197 6.2,-1.803
3D body: height 0.32, standoff -0.08, extent 5.801,-1.697 6.2,-1.303
3D body: height 0.32, standoff -0.08, extent 5.801,-0.697 6.2,-0.303
3D body: height 0.32, standoff -0.08, extent 5.801,-0.197 6.2,0.197
3D body: height 0.32, standoff -0.08, extent 5.801,0.303 6.2,0.697
3D body: height 0.32, standoff -0.08, extent 5.801,1.303 6.2,1.697
3D body: height 0.32, standoff -0.08, extent 5.801,1.803 6.2,2.197
3D body: height 0.32, standoff -0.08, extent 5.801,2.303 6.2,2.697
3D body: height 0.32, standoff -0.08, extent 5.801,3.303 6.2,3.697
3D body: height 0.32, standoff -0.08, extent 5.801,3.803 6.2,4.197
3D body: height 0.32, standoff -0.08, extent 5.801,4.303 6.2,4.697
3D body: height 0.32, standoff -0.08, extent 5.801,5.303 6.2,5.697
3D body: height 0.32, standoff -0.08, extent 5.801,5.803 6.2,6.197
3D body: height 0.32, standoff -0.08, extent 5.801,6.303 6.2,6.697
3D body: height 0.32, standoff -0.08, extent -1.199,-4.197 -0.8,-3.803
3D body: height 0.32, standoff -0.08, extent -0.199,-4.197 0.2,-3.803
3D body: height 0.32, standoff -0.08, extent 0.801,-4.197 1.2,-3.803
3D body: height 0.32, standoff -0.08, extent 1.801,-4.197 2.2,-3.803
3D body: height 0.32, standoff -0.08, extent 2.801,-4.197 3.2,-3.803
3D body: height 0.32, standoff -0.08, extent 3.801,-4.197 4.2,-3.803
3D body: height 0.32, standoff -0.08, extent 3.801,-3.197 4.2,-2.803
3D body: height 0.32, standoff -0.08, extent -4.199,-4.197 -3.8,-3.803
3D body: height 0.32, standoff -0.08, extent -3.199,-4.197 -2.8,-3.803
3D body: height 0.32, standoff -0.08, extent -2.199,-4.197 -1.8,-3.803
3D body: height 0.32, standoff -0.08, extent -3.699,4.303 -3.3,4.697
3D body: height 0.32, standoff -0.08, extent -2.699,4.303 -2.3,4.697
3D body: height 0.32, standoff -0.08, extent -1.699,4.303 -1.3,4.697
3D body: height 0.32, standoff -0.08, extent -0.699,4.303 -0.3,4.697
3D body: height 0.32, standoff -0.08, extent 0.301,4.303 0.7,4.697
3D body: height 0.32, standoff -0.08, extent 1.301,4.303 1.7,4.697
3D body: height 0.32, standoff -0.08, extent 2.301,4.303 2.7,4.697
3D body: height 0.32, standoff -0.08, extent 3.301,4.303 3.7,4.697
3D body: height 0.32, standoff -0.08, extent 3.801,1.803 4.2,2.197
3D body: height 0.32, standoff -0.08, extent 3.801,2.803 4.2,3.197
3D body: height 0.32, standoff -0.08, extent 3.801,3.803 4.2,4.197
3D body: height 0.32, standoff -0.08, extent 6.301,-6.197 6.7,-5.803
3D body: height 0.32, standoff -0.08, extent 6.301,-4.697 6.7,-4.303
3D body: height 0.32, standoff -0.08, extent 6.301,-4.197 6.7,-3.803
3D body: height 0.32, standoff -0.08, extent 6.301,-2.697 6.7,-2.303
3D body: height 0.32, standoff -0.08, extent 6.301,-2.197 6.7,-1.803
3D body: height 0.32, standoff -0.08, extent 6.301,-0.697 6.7,-0.303
3D body: height 0.32, standoff -0.08, extent 6.301,-0.197 6.7,0.197
3D body: height 0.32, standoff -0.08, extent 6.301,1.303 6.7,1.697
3D body: height 0.32, standoff -0.08, extent 6.301,1.803 6.7,2.197
3D body: height 0.32, standoff -0.08, extent 6.301,3.303 6.7,3.697
3D body: height 0.32, standoff -0.08, extent 6.301,3.803 6.7,4.197
3D body: height 0.32, standoff -0.08, extent 6.301,5.303 6.7,5.697
3D body: height 0.32, standoff -0.08, extent 6.301,5.803 6.7,6.197
3D body: height 0.32, standoff -0.08, extent 6.301,6.303 6.7,6.697
3D body: height 0.32, standoff -0.08, extent -6.699,-6.697 -6.3,-6.303
3D body: height 0.32, standoff -0.08, extent -6.199,-6.697 -5.8,-6.303
3D body: height 0.32, standoff -0.08, extent -4.699,-6.697 -4.3,-6.303
3D body: height 0.32, standoff -0.08, extent -2.199,-6.697 -1.8,-6.303
3D body: height 0.32, standoff -0.08, extent -0.699,-6.697 -0.3,-6.303
3D body: height 0.32, standoff -0.08, extent -0.199,-6.697 0.2,-6.303
3D body: height 0.32, standoff -0.08, extent 1.301,-6.697 1.7,-6.303
3D body: height 0.32, standoff -0.08, extent 3.801,-6.697 4.2,-6.303
3D body: height 0.32, standoff -0.08, extent 5.301,-6.697 5.7,-6.303
3D body: height 0.32, standoff -0.08, extent 5.801,-6.697 6.2,-6.303
3D body: height 0.32, standoff -0.08, extent 6.301,-6.697 6.7,-6.303
3D body: height 0.32, standoff -0.08, extent -4.199,3.803 -3.8,4.197
3D body: height 0.32, standoff -0.08, extent -3.199,3.803 -2.8,4.197
3D body: height 0.32, standoff -0.08, extent -2.199,3.803 -1.8,4.197
3D body: height 0.32, standoff -0.08, extent -1.199,3.803 -0.8,4.197
3D body: height 0.32, standoff -0.08, extent -0.199,3.803 0.2,4.197
3D body: height 0.32, standoff -0.08, extent 0.801,3.803 1.2,4.197
3D body: height 0.32, standoff -0.08, extent 1.801,3.803 2.2,4.197
3D body: height 0.32, standoff -0.08, extent 2.801,3.803 3.2,4.197
3D body: height 0.32, standoff -0.08, extent -4.199,2.803 -3.8,3.197
3D body: height 0.32, standoff -0.08, extent -3.699,2.303 -3.3,2.697
3D body: height 0.32, standoff -0.08, extent 3.301,2.303 3.7,2.697
3D body: height 0.32, standoff -0.08, extent -4.199,1.803 -3.8,2.197
3D body: height 0.32, standoff -0.08, extent -3.699,1.303 -3.3,1.697
3D body: height 0.32, standoff -0.08, extent 3.301,1.303 3.7,1.697
3D body: height 0.32, standoff -0.08, extent -4.199,0.803 -3.8,1.197
3D body: height 0.32, standoff -0.08, extent -3.699,0.303 -3.3,0.697
3D body: height 0.32, standoff -0.08, extent 3.301,0.303 3.7,0.697
3D body: height 0.32, standoff -0.08, extent -4.199,-0.197 -3.8,0.197
3D body: height 0.32, standoff -0.08, extent -3.699,-0.697 -3.3,-0.303
3D body: height 0.32, standoff -0.08, extent 3.301,-0.697 3.7,-0.303
3D body: height 0.32, standoff -0.08, extent -4.199,-1.197 -3.8,-0.803
3D body: height 0.32, standoff -0.08, extent -3.699,-1.697 -3.3,-1.303
3D body: height 0.32, standoff -0.08, extent 3.301,-1.697 3.7,-1.303
3D body: height 0.32, standoff -0.08, extent -4.199,-2.197 -3.8,-1.803
3D body: height 0.32, standoff -0.08, extent -3.699,-2.697 -3.3,-2.303
3D body: height 0.32, standoff -0.08, extent 3.301,-2.697 3.7,-2.303
3D body: height 0.32, standoff -0.08, extent -4.199,-3.197 -3.8,-2.803
3D body: height 0.32, standoff -0.08, extent -4.2,-6.697 -3.801,-6.303
3D body: height 0.32, standoff -0.08, extent -2.7,-6.697 -2.301,-6.303
3D body: height 0.32, standoff -0.08, extent 1.8,-6.697 2.199,-6.303
3D body: height 0.32, standoff -0.08, extent 3.301,-6.697 3.7,-6.303

## ICC_TO-CAN [mm] "MCD-02679"
height 3.31
pads (3):
  rect 1.2x1.2 hole 0.7 paste-2539.97 mask+0.05: 1(-1.27,0)
  round 1.2 hole 0.7 paste-2539.97 mask+0.05: 2(0,-1.27) 3(1.27,0)
Top Overlay:
  lines w0.12: -3.24,2.419 -2.335,1.514 ; -3.239,2.418 -2.418,3.239 -1.513,2.334 ; -2.332,1.513 ccw(c0,0) -1.513,2.332
  text "1" at -2.525,-0.525 h1.5
M14-Top Assembly:
  circle w0.01: c0,0 r2.192
  lines w0.01: -2.332,1.513 ccw(c0,0) -1.513,2.332 ; -2.334,1.513 -3.239,2.418 -2.418,3.239 -1.513,2.334
  text "3" at 1.14,-0.3 h1
  text "2" at -0.13,-1.57 h1
  text "1" at -1.4,-0.3 h1
  text "'.Designator'" at 0,0 h0.75
M16-Top Courtyard:
  lines w0.01: -1.499,2.599 cw(c0,0) -2.599,1.499 -3.525,2.425 -2.425,3.525 -1.499,2.599 ; -1.499,2.599 -1.499,2.599
3D body: height 0.7, standoff -12, extent 1.031,-0.24 1.509,0.24
3D body: height 0.7, standoff -12, extent -0.239,-1.51 0.239,-1.03
3D body: height 1.4, standoff 0.64, extent -2.78,-2.777 2.78,2.777
3D body: height 1.4, standoff 0.64, extent -3.239,1.096 -1.096,3.239
3D body: height 3.31, standoff 0.64, extent -2.475,-2.472 2.475,2.472
3D body: height 0.7, standoff -12, extent -1.509,-0.24 -1.031,0.24

## ICC_TQFN12_2X1P7_P040 [mm]
height 0.55
pads (12):
  rect 0.2x0.75 smd paste+0 mask+0.05: 1(-0.8,-0.675) 2(-0.4,-0.675) 3(0,-0.675) 4(0.4,-0.675) 5(0.8,-0.675) 7(0.8,0.675) 8(0.4,0.675) 9(0,0.675) 10(-0.4,0.675) 11(-0.8,0.675)
  rect 0.85x0.2 smd paste+0 mask+0.05: 6(0.775,0) 12(-0.775,0)
Top Overlay:
  lines w0.12: -1.025,-0.85 -1.025,-0.225 ; -1.025,0.225 -1.025,0.85 ; 1.025,-0.85 1.025,-0.225 ; 1.025,0.225 1.025,0.85
  text "1" at -1.5,-1.15 h1.5
M14-Top Assembly:
  lines w0.01: -1,-0.1 -0.45,-0.1 -0.45,0.1 -1,0.1 ; -0.9,-0.85 -0.9,-0.3 -0.7,-0.3 -0.7,-0.85 ; -0.9,0.85 -0.9,0.3 -0.7,0.3 -0.7,0.85 ; -0.5,-0.85 -0.5,-0.3 -0.3,-0.3 -0.3,-0.85 ; -0.5,0.85 -0.5,0.3 -0.3,0.3 -0.3,0.85 ; -0.1,-0.85 -0.1,-0.3 0.1,-0.3 0.1,-0.85 ; -0.1,0.85 -0.1,0.3 0.1,0.3 0.1,0.85 ; 0.3,-0.85 0.3,-0.3 0.5,-0.3 0.5,-0.85 ; 0.3,0.85 0.3,0.3 0.5,0.3 0.5,0.85 ; 0.7,-0.85 0.7,-0.3 0.9,-0.3 0.9,-0.85 ; 0.7,0.85 0.7,0.3 0.9,0.3 0.9,0.85 ; 1,-0.1 0.475,-0.1 0.475,0.1 1,0.1 ; -1,-0.85 1,-0.85 1,0.85 -1,0.85 -1,-0.85
  text "'.Designator'" at -2,-0.5 h0.75
  text "1" at -0.875,-0.775 h0.5
  text "5" at 0.7,-0.775 h0.5
  text "6" at 0.9,-0.1 h0.5
  text "12" at -0.925,0.225 h0.5
  text "7" at 0.7,0.475 h0.5
  text "11" at -1,0.475 h0.5
M16-Top Courtyard:
  lines w0.01: -1.35,-1.2 1.35,-1.2 1.35,-1.1 1.35,1.2 -1.35,1.2 -1.35,-1.2
3D body: height 0.56, standoff 0.55, extent -0.875,-0.725 -0.625,-0.475
3D body: height 0.55, standoff 0, extent -1,-0.85 1,0.85

## ICC_TQFN16-EPAD_5X5_H0P75_P080 [mm] "MCD-04179"
height 0.8
pads (17):
  rect 0.35x0.8 smd mask+0.05: 1(-1.2,-2.415) 2(-0.4,-2.415) 3(0.4,-2.415) 4(1.2,-2.415) 9(1.2,2.415) 10(0.4,2.415) 11(-0.4,2.415) 12(-1.2,2.415)
  rect 0.8x0.35 smd mask+0.05: 5(2.415,-1.2) 6(2.415,-0.4) 7(2.415,0.4) 8(2.415,1.2) 13(-2.415,1.2) 14(-2.415,0.4) 15(-2.415,-0.4) 16(-2.415,-1.2)
  rect 3.15x3.15 smd mask+0.05: 17(0,0)
Top Overlay:
  lines w0.12: -2.75,-1.625 -2.75,-2.75 -1.625,-2.75 ; -2.75,1.625 -2.75,2.75 -1.625,2.75 ; 1.625,-2.75 2.75,-2.75 2.75,-1.625 ; 1.625,2.75 2.75,2.75 2.75,1.625
  text "1" at -1.575,-3.25 h1.5
M14-Top Assembly:
  lines w0.01: -2.55,-1.375 -2.05,-1.375 -2.05,-1.025 -2.55,-1.025 ; -2.55,-0.575 -2.05,-0.575 -2.05,-0.225 -2.55,-0.225 ; -2.55,0.225 -2.05,0.225 -2.05,0.575 -2.55,0.575 ; -2.55,1.025 -2.05,1.025 -2.05,1.375 -2.55,1.375 ; -1.375,-2.55 -1.375,-2.05 -1.025,-2.05 -1.025,-2.55 ; -1.375,2.55 -1.375,2.05 -1.025,2.05 -1.025,2.55 ; -0.575,-2.55 -0.575,-2.05 -0.225,-2.05 -0.225,-2.55 ; -0.575,2.55 -0.575,2.05 -0.225,2.05 -0.225,2.55 ; 0.225,-2.55 0.225,-2.05 0.575,-2.05 0.575,-2.55 ; 0.225,2.55 0.225,2.05 0.575,2.05 0.575,2.55 ; 1.025,-2.55 1.025,-2.05 1.375,-2.05 1.375,-2.55 ; 1.025,2.55 1.025,2.05 1.375,2.05 1.375,2.55 ; 2.55,-1.375 2.05,-1.375 2.05,-1.025 2.55,-1.025 ; 2.55,-0.575 2.05,-0.575 2.05,-0.225 2.55,-0.225 ; 2.55,0.225 2.05,0.225 2.05,0.575 2.55,0.575 ; 2.55,1.025 2.05,1.025 2.05,1.375 2.55,1.375 ; -2.55,-2.55 2.55,-2.55 2.55,2.55 -2.55,2.55 -2.55,-2.55 ; -1.6,-1.6 1.6,-1.6 1.6,1.6 -1.6,1.6 -1.6,-1.6
  text "11" at -2.475,1.425 h0.5
  text "'.Designator'" at -2,-0.5 h0.75
  text "1" at -1.25,-2.475 h0.5
  text "8" at 2.475,1.1 h0.5
  text "9" at 1.1,2.125 h0.5
  text "16" at -2.475,-0.975 h0.5
  text "17" at -0.2,-0.125 h0.5
  text "4" at 1.1,-2.45 h0.5
  text "5" at 2.45,-1.3 h0.5
  text "10" at -1.425,2.125 h0.5
M16-Top Courtyard:
  lines w0.01: -2.975,-2.975 -2.975,2.975 2.975,2.975 2.975,-2.975 -2.975,-2.975
3D body "User Library-TQFN15_5x5x0_75.STEP": height 0.8, standoff 0, extent -2.51,-2.51 2.51,2.51

## ICC_TQFN32-EPAD_5X5_H0P75_P050 [mm] "MCD-01621"
height 0.8
pads (33):
  oval 0.3x0.75 smd mask+0.05: 1(-1.75,-2.425) 2(-1.25,-2.425) 3(-0.75,-2.425) 4(-0.25,-2.425) 5(0.25,-2.425) 6(0.75,-2.425) 7(1.25,-2.425) 8(1.75,-2.425) 17(1.75,2.425) 18(1.25,2.425) 19(0.75,2.425) 20(0.25,2.425) 21(-0.25,2.425) 22(-0.75,2.425) 23(-1.25,2.425) 24(-1.75,2.425)
  oval 0.75x0.3 smd mask+0.05: 9(2.425,-1.75) 10(2.425,-1.25) 11(2.425,-0.75) 12(2.425,-0.25) 13(2.425,0.25) 14(2.425,0.75) 15(2.425,1.25) 16(2.425,1.75) 25(-2.425,1.75) 26(-2.425,1.25) 27(-2.425,0.75) 28(-2.425,0.25) 29(-2.425,-0.25) 30(-2.425,-0.75) 31(-2.425,-1.25) 32(-2.425,-1.75)
  rect 3.7x3.7 smd mask+0.05: 33(0,0)
Top Overlay:
  circle w0.12: c-2.3,-2.3 r0.2
  lines w0.12: -2.625,-2.05 -2.625,-2.625 -2.05,-2.625 ; -2.625,2.05 -2.625,2.625 -2.05,2.625 ; 2.05,-2.625 2.625,-2.625 2.625,-2.05 ; 2.05,2.625 2.625,2.625 2.625,2.05
  text "1" at -2,-3.075 h1.5
M14-Top Assembly:
  circle w0.01: c-2.125,-2.25 r0.18
  lines w0.01: -2.55,-1.87 -2.1,-1.87 -2.1,-1.63 -2.55,-1.63 ; -2.55,-1.37 -2.1,-1.37 -2.1,-1.13 -2.55,-1.13 ; -2.55,-0.87 -2.1,-0.87 -2.1,-0.63 -2.55,-0.63 ; -2.55,-0.37 -2.1,-0.37 -2.1,-0.13 -2.55,-0.13 ; -2.55,0.13 -2.1,0.13 -2.1,0.37 -2.55,0.37 ; -2.55,0.63 -2.1,0.63 -2.1,0.87 -2.55,0.87 ; -2.55,1.13 -2.1,1.13 -2.1,1.37 -2.55,1.37 ; -2.55,1.63 -2.1,1.63 -2.1,1.87 -2.55,1.87 ; -1.87,-2.55 -1.87,-2.1 -1.63,-2.1 -1.63,-2.55 ; -1.87,2.55 -1.87,2.1 -1.63,2.1 -1.63,2.55 ; -1.37,-2.55 -1.37,-2.1 -1.13,-2.1 -1.13,-2.55 ; -1.37,2.55 -1.37,2.1 -1.13,2.1 -1.13,2.55 ; -0.87,-2.55 -0.87,-2.1 -0.63,-2.1 -0.63,-2.55 ; -0.87,2.55 -0.87,2.1 -0.63,2.1 -0.63,2.55 ; -0.37,-2.55 -0.37,-2.1 -0.13,-2.1 -0.13,-2.55 ; -0.37,2.55 -0.37,2.1 -0.13,2.1 -0.13,2.55 ; 0.13,-2.55 0.13,-2.1 0.37,-2.1 0.37,-2.55 ; 0.13,2.55 0.13,2.1 0.37,2.1 0.37,2.55 ; 0.63,-2.55 0.63,-2.1 0.87,-2.1 0.87,-2.55 ; 0.63,2.55 0.63,2.1 0.87,2.1 0.87,2.55 ; 1.13,-2.55 1.13,-2.1 1.37,-2.1 1.37,-2.55 ; 1.13,2.55 1.13,2.1 1.37,2.1 1.37,2.55 ; 1.63,-2.55 1.63,-2.1 1.87,-2.1 1.87,-2.55 ; 1.63,2.55 1.63,2.1 1.87,2.1 1.87,2.55 ; 2.55,-1.87 2.1,-1.87 2.1,-1.63 2.55,-1.63 ; 2.55,-1.37 2.1,-1.37 2.1,-1.13 2.55,-1.13 ; 2.55,-0.87 2.1,-0.87 2.1,-0.63 2.55,-0.63 ; 2.55,-0.37 2.1,-0.37 2.1,-0.13 2.55,-0.13 ; 2.55,0.13 2.1,0.13 2.1,0.37 2.55,0.37 ; 2.55,0.63 2.1,0.63 2.1,0.87 2.55,0.87 ; 2.55,1.13 2.1,1.13 2.1,1.37 2.55,1.37 ; 2.55,1.63 2.1,1.63 2.1,1.87 2.55,1.87 ; -2.55,-2.55 2.55,-2.55 2.55,2.55 -2.55,2.55 -2.55,-2.55 ; -1.8,-1.787 1.807,-1.787 1.807,1.82 -1.8,1.82 -1.8,-1.787
  text "'.Designator'" at -2,-0.5 h0.75
  text "1" at -1.8,-2.475 h0.5
  text "8" at 1.65,-2.475 h0.5
  text "9" at 2.45,-1.85 h0.5
  text "16" at 2.45,1.575 h0.5
  text "17" at 1.55,2.15 h0.5
  text "24" at -1.975,2.175 h0.5
  text "25" at -2.45,2 h0.5
  text "32" at -2.45,-1.525 h0.5
  text "33" at -0.275,-0.15 h0.5
M16-Top Courtyard:
  lines w0.01: -2.95,-2.95 -2.95,2.95 2.95,2.95 2.95,-2.95 -2.95,-2.95
3D body: height 0.8, standoff 0, extent -2.55,-2.55 2.55,2.55
3D body "QFN-32UH.STEP": height 0.75, standoff 0, extent -2.51,-2.51 2.51,2.51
